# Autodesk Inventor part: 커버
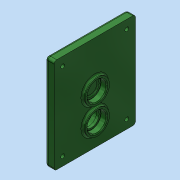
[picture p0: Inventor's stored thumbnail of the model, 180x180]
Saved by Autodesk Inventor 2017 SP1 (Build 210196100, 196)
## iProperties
Created: 2016-02
Part Number: 커버
Material: 알루미늄 6061
Document SubType Name: Modeling
Designer: mduedu
Density: 2.71 g/cm^3
Appearance: 매끄러움 - 짙은 산림 녹색
Mass: 271.622 g
Surface Area: 265.357 cm^2
Volume: 100.23 cm^3
Author: mduedu
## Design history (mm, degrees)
sketch "스케치1"
  geometry: L1 (63, 47)-(-47, 47); L2 (-47, 47)-(-47, -47); L3 (-47, -47)-(63, -47); L4 (63, -47)-(63, 47); 2 further points
  constraints: 8 end point, 2 parallel, 1 horizontal, 1 horizontal alignment, 1 midpoint, 1 perpendicular
  dimensions: "d102" = 94 distance of L3.end L1.start; "d104" = 47 distance from line of L2 point (0, 0); "d105" = 110 distance of L1.start L1.end
extrude "돌출1" new body sketch "스케치1" distance "d1" = 10; taper "d2" = 0 deg
sketch "스케치2"
  geometry: C1 r 14 at (0, 11); 1 further point
  constraints: 1 centre point, 1 vertical alignment
  dimensions: "d3" = 28 diameter of C1; "d6" = 11 distance of C1.centre point (0, 0)
extrude "돌출2" join sketch "스케치2" distance "d7" = 3; taper "d8" = 0 deg
sketch "스케치3"
  geometry: C1 r 14 at (0, -20); 1 further point
  constraints: 1 centre point, 1 vertical alignment
  dimensions: "d9" = 28 diameter of C1; "d10" = 20 distance of C1.centre point (0, 0)
extrude "돌출3" join sketch "스케치3" distance "d11" = 3; taper "d12" = 0 deg
hole "구멍1" diameter "d15" = 22; stored, may be unused: countersink angle "d19" = 90 deg, drill point angle "d21" = 0 deg; dims "d13" = 10, "d14" = 10, "d16" = 6, "d17" = 4, "d18" = 2, "d20" = 7
hole "구멍2" diameter "d24" = 18; stored, may be unused: countersink angle "d28" = 90 deg, drill point angle "d30" = 0 deg; dims "d22" = 10, "d23" = 10, "d25" = 6, "d26" = 4, "d27" = 2, "d29" = 1
hole "구멍3" diameter "d33" = 22; stored, may be unused: countersink angle "d37" = 90 deg, drill point angle "d39" = 0 deg; dims "d34" = 6, "d35" = 4, "d36" = 2, "d38" = 7, "d73" = 10, "d74" = 10
sketch "스케치4"
  geometry: C1 r 14 at (0, -20) reference; C2 r 18 at (0, -20); 1 further point
  constraints: 1 centre point, 1 coincident
  dimensions: "d40" = 36 diameter of C2
extrude "돌출4" join sketch "스케치4" distance "d41" = 4; taper "d42" = 0 deg
hole "구멍4" diameter "d45" = 22; stored, may be unused: countersink angle "d49" = 90 deg, drill point angle "d51" = 0 deg; dims "d43" = 10, "d44" = 10, "d46" = 6, "d47" = 4, "d48" = 2, "d50" = 7
hole "구멍5" diameter "d54" = 18; stored, may be unused: countersink angle "d58" = 90 deg, drill point angle "d60" = 0 deg; dims "d55" = 6, "d56" = 4, "d57" = 2, "d59" = 7, "d116" = 10, "d117" = 10
fillet "모깎기1" dims "d61" = 0.3
fillet "모깎기2" dims "d62" = 2
chamfer "모따기1" distance "d63" = 1; stored, may be unused: second distance "d64" = 2, angle "d65" = 45 deg
fillet "모깎기6" dims "d88" = 2
fillet "모깎기4" dims "d75" = 2
sketch "스케치9"
  geometry: L1 (47, 63)-(47, -47) reference; L2 (-47, 63)-(47, 63) reference; L3 (-47, -47)-(-47, 63) reference; L4 (47, -47)-(-47, -47) reference; L5 (37, 53)-(37, -37); L6 (37, -37)-(-37, -37); L7 (-37, -37)-(-37, 53); L8 (-37, 53)-(37, 53); C1 r 20 at (0, -20) reference; 5 further points
  constraints: 8 end point, 4 coincident, 3 other
  dimensions: "d107" = 10 distance between parallel lines of L8 L2
hole "구멍7" sketch "스케치9" at (-37, 53), (37, 53), (37, -37), (-37, -37) diameter "d108" = 4.5; stored, may be unused: countersink angle "d112" = 90 deg, drill point angle "d114" = 118 deg; dims "d109" = 6, "d110" = 8, "d111" = 4.6, "d113" = 8
fillet "모깎기8" dims "d106" = 3
fillet "모깎기9" dims "d115" = 3
node "솔리드1"
node "투영된 루프2"
